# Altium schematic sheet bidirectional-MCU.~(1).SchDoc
size 431 x 279 mm; Date: Not shown in title block; ApprovedBy: Not shown in title block; CheckedBy: Not shown in title block; Author: Not shown in title block; CompanyName: Not shown in title block; Engineer: Not shown in title block; Organization: Not shown in title block; Address1: Not shown in title block; Address2: Not shown in title block; Address3: Not shown in title block; Address4: Not shown in title block; DocumentNumber: 1; Revision: Use project parameter SCH_Rev; SheetNumber: 1; SheetTotal: 6; PageSetup: Record=PageOptions¦CenterHorizontal=True¦CenterVertical=True¦PrintScale=0.96¦XCorrection=1.00¦YCorrection=1.00¦PrintKind=0¦BorderSize=5000000¦LeftOffset=0¦BottomOffset=0¦Orientation=2¦PaperLength=1000¦PaperWidth=1000¦Scale=100¦PaperSource=15¦PrintQuality=600¦MediaType=1¦DitherType=10¦PaperKind=11x17¦PrintScaleMode=1
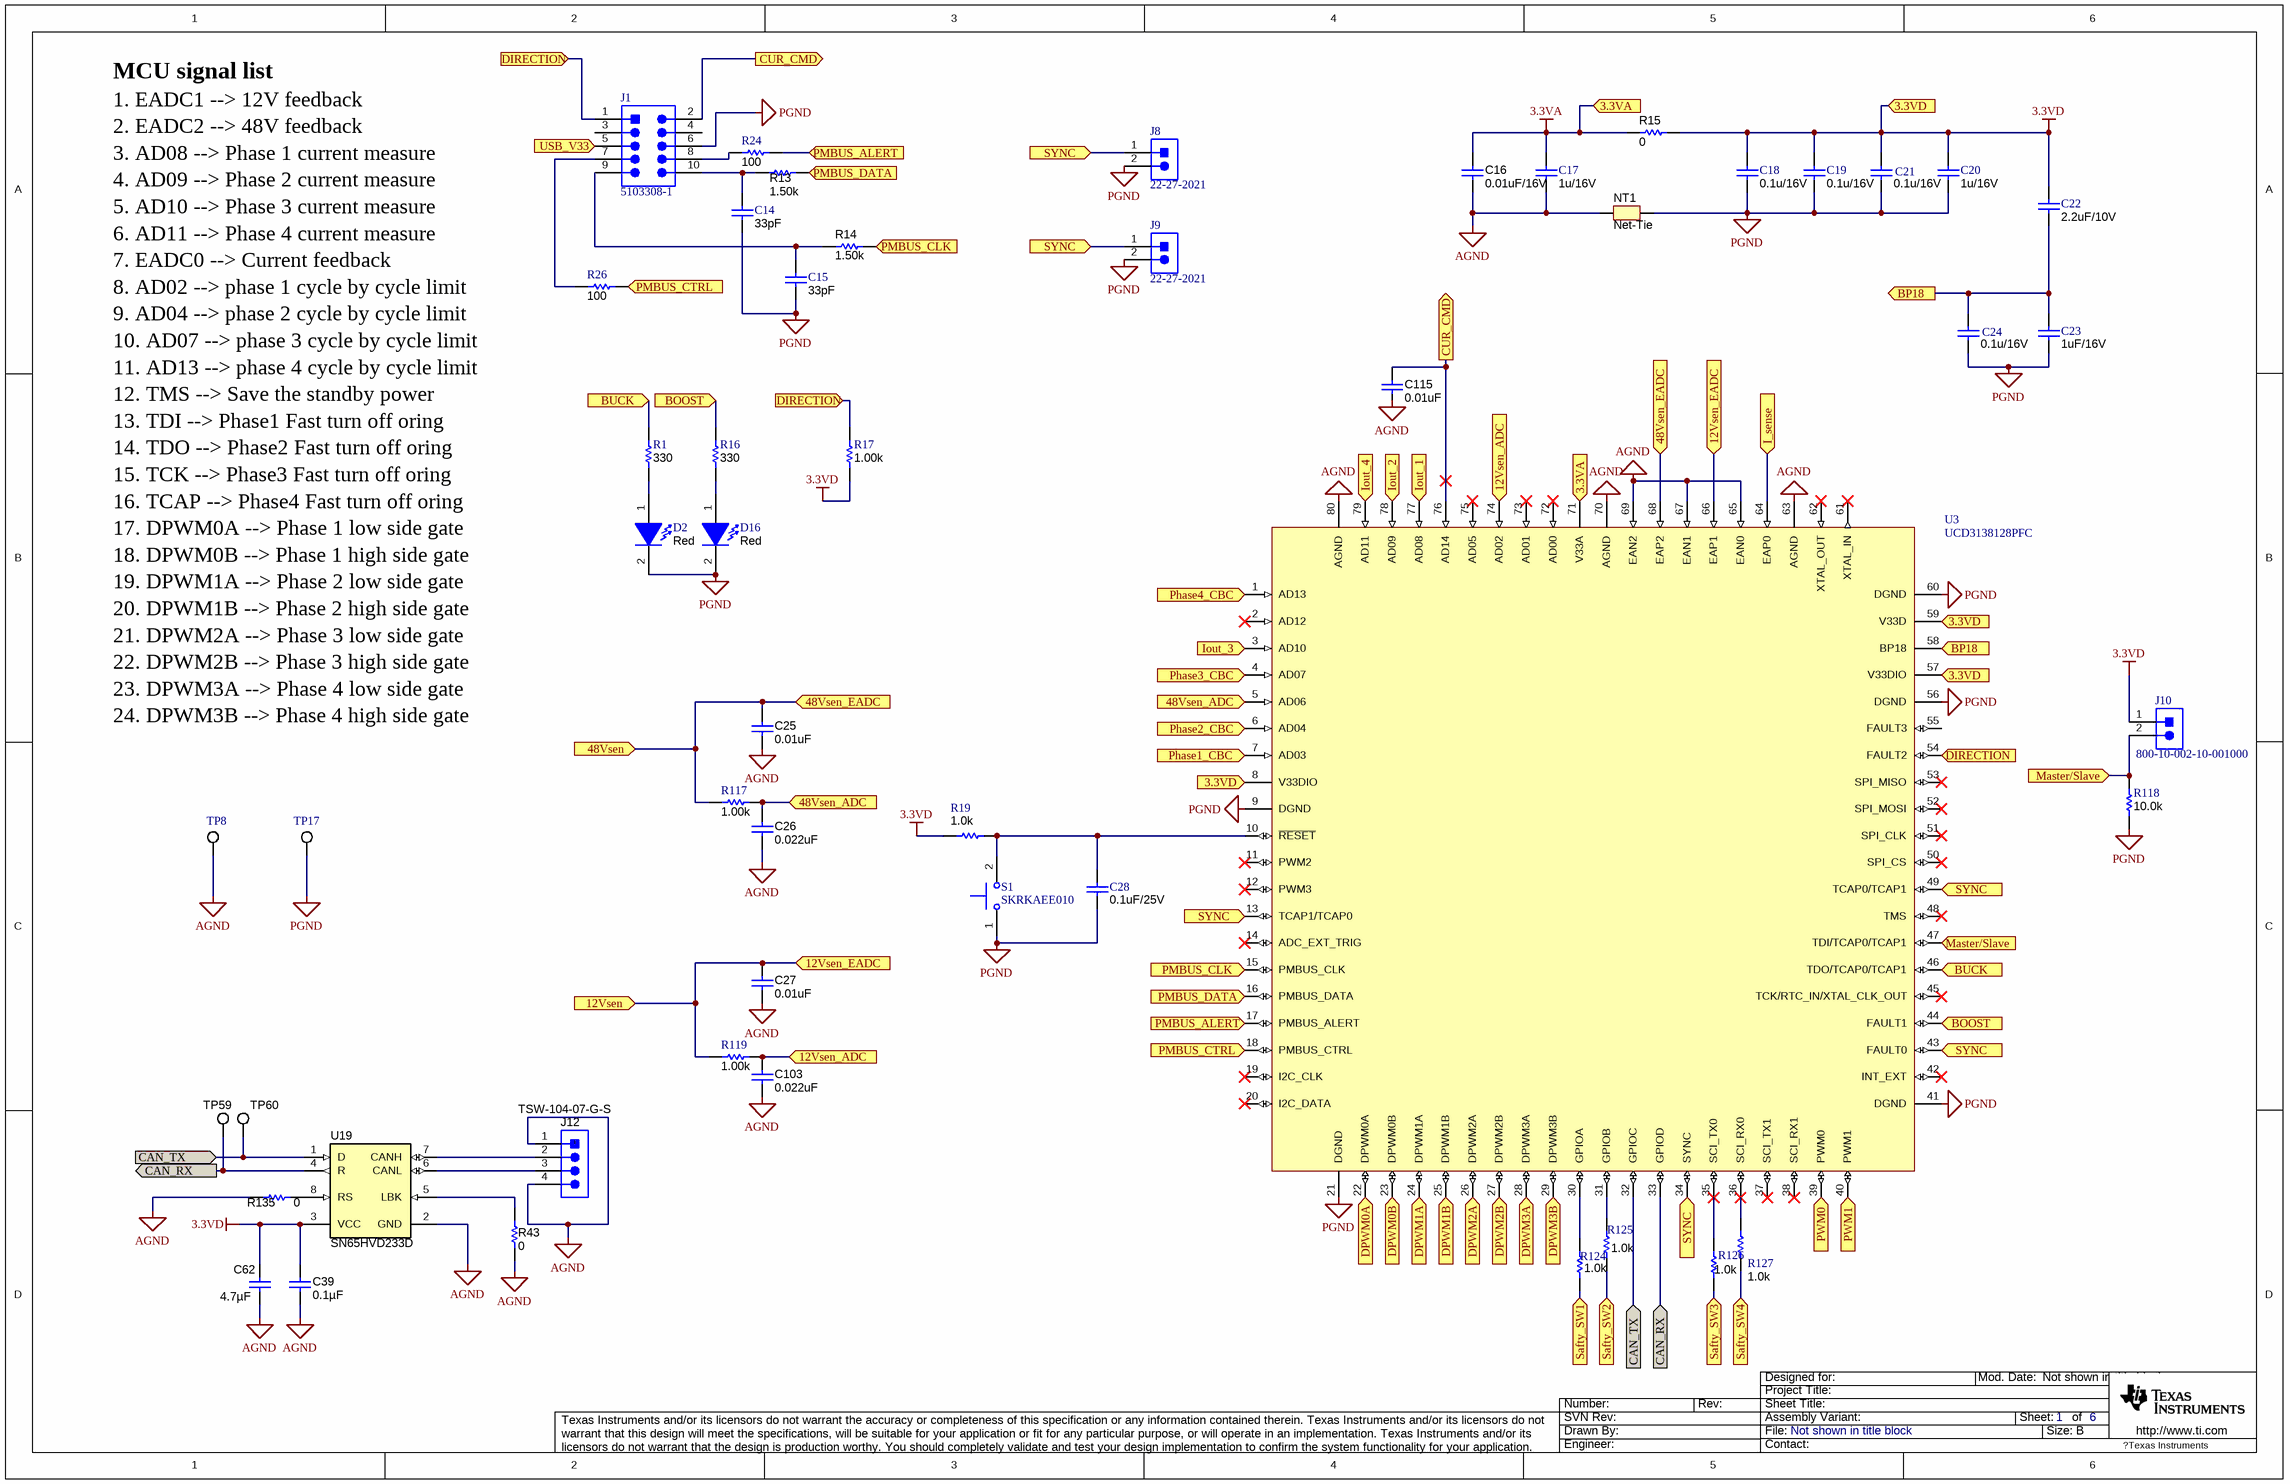
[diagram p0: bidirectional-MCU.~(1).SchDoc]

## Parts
C14  ValueDisplayed: 33pF  [0603]  (hidden comment: 06031A330JAT2A)
C15  ValueDisplayed: 33pF  [0603]  (hidden comment: 06031A330JAT2A)
C16  ValueDisplayed: 0.01uF/16V  [0603]  (hidden comment: 06031C103JAT2A)
C17  ValueDisplayed: 1u/16V  [0603]  (hidden comment: C0603C105K4PACTU)
C18  ValueDisplayed: 0.1u/16V  [0603]  (hidden comment: 0603YC104JAT2A)
C19  ValueDisplayed: 0.1u/16V  [0603]  (hidden comment: 0603YC104JAT2A)
C20  ValueDisplayed: 1u/16V  [0603]  (hidden comment: C0603C105K4PACTU)
C21  ValueDisplayed: 0.1u/16V  [0603]  (hidden comment: 0603YC104JAT2A)
C22  ValueDisplayed: 2.2uF/10V  [0603]  (hidden comment: C0603C225K8PACTU)
C23  ValueDisplayed: 1uF/16V  [0603]  (hidden comment: C0603C105K4PACTU)
C24  ValueDisplayed: 0.1u/16V  [0603]  (hidden comment: 0603YC104JAT2A)
C25  ValueDisplayed: 0.01uF  [0603]  (hidden comment: 06031C103JAT2A)
C26  ValueDisplayed: 0.022uF  [0603]  (hidden comment: C0603C223K3RACTU)
C27  ValueDisplayed: 0.01uF  [0603]  (hidden comment: 06031C103JAT2A)
C28  ValueDisplayed: 0.1uF/25V  [0603]  (hidden comment: 06033C104JAT2A)
C39  ValueDisplayed: 0.1µF  [0603]  (hidden comment: GRM188R71E104KA01D)
C62  ValueDisplayed: 4.7µF  [0805_HV]  (hidden comment: C2012X5R1E475K125AB)
C103  ValueDisplayed: 0.022uF  [0603]  (hidden comment: C0603C223K3RACTU)
C115  ValueDisplayed: 0.01uF  [0603]  (hidden comment: 06031C103JAT2A)
D2  value Red  [LED_LTST-C170]  (hidden comment: LTST-C170KRKT)
D16  value Red  [LED_LTST-C170]  (hidden comment: LTST-C170KRKT)
J1  5103308-1  [CONN_5103308-1]
J8  22-27-2021  [MOLEX_22-27-2021]
J9  22-27-2021  [MOLEX_22-27-2021]
J10  800-10-002-10-001000  [Mill-Max_800-10-002-10-001000]
J12  TSW-104-07-G-S  [TSW-104-07-G-S]
NT1  Net-Tie  [Net-Tie_10mil]  (net tie, no BOM)
R1  value 330  [0603]  (hidden comment: RC0603FR-07330RL)
R13  value 1.50k  [0603]  (hidden comment: RG1608P-152-B-T5)
R14  value 1.50k  [0603]  (hidden comment: RG1608P-152-B-T5)
R15  value 0  [0603]  (hidden comment: MCR03EZPJ000)
R16  value 330  [0603]  (hidden comment: RC0603FR-07330RL)
R17  value 1.00k  [0603]  (hidden comment: CRCW06031K00FKEA)
R19  value 1.0k  [0603]  (hidden comment: CRCW06031K00JNEA)
R24  value 100  [0603]  (hidden comment: CRCW0603100RFKEA)
R26  value 100  [0603]  (hidden comment: CRCW0603100RFKEA)
R43  value 0  [0805_HV]  (hidden comment: CRCW08050000Z0EA)
R117  value 1.00k  [0603]  (hidden comment: CRCW06031K00FKEA)
R118  value 10.0k  [0603]  (hidden comment: CRCW060310K0FKEA)
R119  value 1.00k  [0603]  (hidden comment: CRCW06031K00FKEA)
R124  value 1.0k  [0603L]  (hidden comment: CRCW06031K00JNEA)
R125  value 1.0k  [0603]  (hidden comment: CRCW06031K00JNEA)
R126  value 1.0k  [0603]  (hidden comment: CRCW06031K00JNEA)
R127  value 1.0k  [0603]  (hidden comment: CRCW06031K00JNEA)
R135  value 0  [0805_HV]  (hidden comment: CRCW08050000Z0EA)
S1  SKRKAEE010  [SW_SKRKAEE010]
TP8  5002  [Keystone5002]  (value not drawn)
TP17  5002  [Keystone5002]  (value not drawn)
TP59  5002  [Keystone5002]  (value not drawn)
TP60  5002  [Keystone5002]  (value not drawn)
U3  UCD3138128PFC  [PFC0080A_N]
U19  SN65HVD233D  [D0008A_L]

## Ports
3.3VA, 3.3VD, 12Vsen, 12Vsen_ADC, 12Vsen_EADC, 48Vsen, 48Vsen_ADC, 48Vsen_EADC, BOOST, BP18, BUCK, CAN_RX, CAN_TX, CAN_TX (in), CUR_CMD, DIRECTION, DPWM0A, DPWM0B, DPWM1A, DPWM1B, DPWM2A, DPWM2B, DPWM3A, DPWM3B, I_sense, Iout_1, Iout_2, Iout_3, Iout_4, Master/Slave, Phase1_CBC, Phase2_CBC, Phase3_CBC, Phase4_CBC, PMBUS_ALERT, PMBUS_CLK, PMBUS_CTRL, PMBUS_DATA, PWM0, PWM1, Safty_SW1, Safty_SW2, Safty_SW3, Safty_SW4, SYNC, USB_V33

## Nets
3.3VA: C16.1 C17.1 R15.1 U3.71(V33A) ; port 3.3VA
3.3VD: C18.1 C19.1 C20.1 C21.1 C22.2 C39.1 C62.1 J10.1 R15.2 R17.1 R19.1 U3.8(V33DIO) U3.57(V33DIO) U3.59(V33D) U19.3(VCC) ; port 3.3VD
AGND: C16.2 C17.2 C25.2 C26.2 C27.2 C39.2 C62.2 C103.2 J12.1 J12.4 NT1.1 R43.1 R135.2 TP8.1 U3.63(AGND) U3.65(EAN0) U3.67(EAN1) U3.69(EAN2) U3.70(AGND) U3.80(AGND) U19.2(GND)
PGND: C14.2 C15.2 C18.2 C19.2 C20.2 C21.2 C23.2 C24.2 C28.2 D2.2(K) D16.2(K) J1.6 J8.2 J9.2 NT1.2 R118.1 S1.1 TP17.1 U3.9(DGND) U3.21(DGND) U3.41(DGND) U3.56(DGND) U3.60(DGND)
12Vsen: C27.1 R119.1 U3.66(EAP1) ; port 12Vsen_EADC, port 12Vsen
12Vsen_ADC: C103.1 R119.2 U3.74(AD02) ; port 12Vsen_ADC
48Vsen: C25.1 R117.1 U3.68(EAP2) ; port 48Vsen_EADC, port 48Vsen
48Vsen_ADC: C26.1 R117.2 U3.5(AD06) ; port 48Vsen_ADC
BOOST: R16.2 U3.44(FAULT1) ; port BOOST
BP18: C22.1 C23.1 C24.1 U3.58(BP18) ; port BP18
BUCK: R1.2 U3.46(TDO/TCAP0/TCAP1) ; port BUCK
CAN_RX: TP59.1 U3.33(GPIOD) U19.4(R) ; port CAN_RX
CAN_TX: TP60.1 U3.32(GPIOC) U19.1(D) ; port CAN_TX
CUR_CMD: C115.1 J1.2 U3.76(AD14) ; port CUR_CMD
DIRECTION: J1.1 R17.2 U3.54(FAULT2) ; port DIRECTION
DPWM0A: U3.22(DPWM0A) ; port DPWM0A
DPWM0B: U3.23(DPWM0B) ; port DPWM0B
DPWM1A: U3.24(DPWM1A) ; port DPWM1A
DPWM1B: U3.25(DPWM1B) ; port DPWM1B
DPWM2A: U3.26(DPWM2A) ; port DPWM2A
DPWM2B: U3.27(DPWM2B) ; port DPWM2B
DPWM3A: U3.28(DPWM3A) ; port DPWM3A
DPWM3B: U3.29(DPWM3B) ; port DPWM3B
I_sense: U3.64(EAP0) ; port I_sense
Iout_1: U3.77(AD08) ; port Iout_1
Iout_2: U3.78(AD09) ; port Iout_2
Iout_3: U3.3(AD10) ; port Iout_3
Iout_4: U3.79(AD11) ; port Iout_4
Master/Slave: J10.2 R118.2 U3.47(TDI/TCAP0/TCAP1) ; port Master/Slave
Phase1_CBC: U3.7(AD03) ; port Phase1_CBC
Phase2_CBC: U3.6(AD04) ; port Phase2_CBC
Phase3_CBC: U3.4(AD07) ; port Phase3_CBC
Phase4_CBC: U3.1(AD13) ; port Phase4_CBC
PMBUS_ALERT: R24.2 U3.17(PMBUS_ALERT) ; port PMBUS_ALERT
PMBUS_CLK: R14.2 U3.15(PMBUS_CLK) ; port PMBUS_CLK
PMBUS_CTRL: R26.2 U3.18(PMBUS_CTRL) ; port PMBUS_CTRL
PMBUS_DATA: R13.2 U3.16(PMBUS_DATA) ; port PMBUS_DATA
PWM0: U3.39(PWM0) ; port PWM0
PWM1: U3.40(PWM1) ; port PWM1
Safty_SW1: R124.1 ; port Safty_SW1
Safty_SW2: R125.1 ; port Safty_SW2
Safty_SW3: R126.1 ; port Safty_SW3
Safty_SW4: R127.1 ; port Safty_SW4
SYNC: J8.1 J9.1 U3.13(TCAP1/TCAP0) U3.34(SYNC) U3.43(FAULT0) U3.49(TCAP0/TCAP1) ; port SYNC
USB_V33: J1.5 ; port USB_V33
NetC14_1: C14.1 J1.10 R13.1
NetC15_1: C15.1 J1.9 R14.1
NetC28_1: C28.1 R19.2 S1.2 U3.10(~{RESET})
NetD2_1: D2.1(A) R1.1
NetD16_1: D16.1(A) R16.1
NetJ1_7: J1.7 R26.1
NetJ1_8: J1.8 R24.1
NetJ12_2: J12.2 U19.7(CANH)
NetJ12_3: J12.3 U19.6(CANL)
NetR43_2: R43.2 U19.5(LBK)
NetR124_2: R124.2 U3.30(GPIOA)
NetR125_2: R125.2 U3.31(GPIOB)
NetR126_2: R126.2 U3.35(SCI_TX0)
NetR127_2: R127.2 U3.36(SCI_RX0)
NetR135_1: R135.1 U19.8(RS)

Not connected (* = marked no-connect by the designer): C115 2; J1 3 4; U3 2(AD12)* 11(PWM2)* 12(PWM3)* 14(ADC_EXT_TRIG)* 19(I2C_CLK)* 20(I2C_DATA)* 37(SCI_TX1)* 38(SCI_RX1)* 42(INT_EXT)* 45(TCK/RTC_IN/XTAL_CLK_OUT)* 48(TMS)* 50(SPI_CS)* 51(SPI_CLK)* 52(SPI_MOSI)* 53(SPI_MISO)* 55(FAULT3) 61(XTAL_IN)* 62(XTAL_OUT)* 72(AD00)* 73(AD01)* 75(AD05)*

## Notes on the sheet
- MCU signal list
- 1. EADC1 --> 12V feedback
- 2. EADC2 --> 48V feedback
- 3. AD08 --> Phase 1 current measure
- 4. AD09 --> Phase 2 current measure
- 5. AD10 --> Phase 3 current measure
- 7. EADC0 --> Current feedback
- (near R26) 8. AD02 --> phase 1 cycle by cycle limit
- 6. AD11 --> Phase 4 current measure
- (near R26) 9. AD04 --> phase 2 cycle by cycle limit
- (near R26) 10. AD07 --> phase 3 cycle by cycle limit
- 12. TMS --> Save the standby power
- 13. TDI --> Phase1 Fast turn off oring
- 11. AD13 --> phase 4 cycle by cycle limit
- 14. TDO --> Phase2 Fast turn off oring
- 15. TCK --> Phase3 Fast turn off oring
- 17. DPWM0A --> Phase 1 low side gate
- 18. DPWM0B --> Phase 1 high side gate
- 16. TCAP --> Phase4 Fast turn off oring
- 19. DPWM1A --> Phase 2 low side gate
- 20. DPWM1B --> Phase 2 high side gate
- 21. DPWM2A --> Phase 3 low side gate
- 22. DPWM2B --> Phase 3 high side gate
- 23. DPWM3A --> Phase 4 low side gate
- 24. DPWM3B --> Phase 4 high side gate
- Labels drawn without touching a wire or pin: AGND

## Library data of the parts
C14 C15 = 06031A330JAT2A: CAP, CERM, 33pF, 100V, +/-5%, C0G/NP0, 0603; Manufacturer: AVX; Polarized: N; CompType: Capacitor; U/M: EA; Cap_F: 0.000000000033; Tolerance_%: 5; ESR_Ohm: 0.209; Value1: 0.209 ohm; VDC_V: 100; TaMin_C: -55; TaMax_C: 125
C16 C25 C27 C115 = 06031C103JAT2A: CAP, CERM, 0.01uF, 100V, +/-5%, X7R, 0603; Manufacturer: AVX; Polarized: N; CompType: Capacitor; U/M: EA; Cap_F: 0.00000001; Tolerance_%: 5; ESR_Ohm: 0.098; Value1: 0.098 ohm; VDC_V: 100; TaMin_C: -55; TaMax_C: 125
C17 C20 C23 = C0603C105K4PACTU: CAP, CERM, 1uF, 16V, +/-10%, X5R, 0603; Manufacturer: Kemet; Polarized: N; CompType: Capacitor; U/M: EA; Cap_F: 0.000001; Tolerance_%: 10; Value1: Unknown; VDC_V: 16; TaMin_C: -55; TaMax_C: 85
C18 C19 C21 C24 = 0603YC104JAT2A: CAP, CERM, 0.1uF, 16V, +/-5%, X7R, 0603; Manufacturer: AVX; Polarized: N; CompType: Capacitor; U/M: EA; Cap_F: 0.0000001; Tolerance_%: 5; ESR_Ohm: 0.039; Value1: 0.039 ohm; VDC_V: 16; TaMin_C: -55; TaMax_C: 125
C22 = C0603C225K8PACTU: CAP, CERM, 2.2uF, 10V, +/-10%, X5R, 0603; Manufacturer: Kemet; Polarized: N; CompType: Capacitor; U/M: EA; Cap_F: 0.0000022; Tolerance_%: 10; Value1: Unknown; TaMin_C: -55; TaMax_C: 85
C26 C103 = C0603C223K3RACTU: CAP, CERM, 0.022uF, 25V, +/-10%, X7R, 0603; Manufacturer: Kemet; Polarized: N; CompType: Capacitor; U/M: EA; Cap_F: 0.000000022; Tolerance_%: 10; Value1: Unknown; VDC_V: 25; TaMin_C: -55; TaMax_C: 125
C28 = 06033C104JAT2A: CAP, CERM, 0.1uF, 25V, +/-5%, X7R, 0603; Manufacturer: AVX; Polarized: N; CompType: Capacitor; U/M: EA; Cap_F: 0.0000001; Tolerance_%: 5; ESR_Ohm: 0.05; Value1: 0.05 ohm; VDC_V: 25; TaMin_C: -55; TaMax_C: 125
C39 = GRM188R71E104KA01D: CAP, CERM, 0.1uF, 25V, +/-10%, X7R, 0603; Manufacturer: MuRata; Polarized: N; CompType: Capacitor; U/M: EA; Cap_F: 0.0000001; Tolerance_%: 10; Value1: Unknown; VDC_V: 25; TaMin_C: -55; TaMax_C: 125
C62 = C2012X5R1E475K125AB: CAP, CERM, 4.7uF, 25V, +/-10%, X5R, 0805; Manufacturer: TDK; Polarized: N; CompType: Capacitor; U/M: EA; Cap_F: 0.0000047; Tolerance_%: 10; Value1: Unknown; VDC_V: 25; TaMin_C: -55; TaMax_C: 85; Cap_Case: 0805
D2 D16 = LTST-C170KRKT: LED, Red, SMD; Manufacturer: Lite-On; Type: AlInGaP; Vf_V: 2; Value2: 2V; Io_A: 0.02; Value1: W; U/M: EA
J1 = 5103308-1: Header (shrouded), 100mil, 5x2, Gold, TH; Manufacturer: TE Connectivity; SymbolCreator: a0412235; CompType: Connector; U/M: EA
J8 J9 = 22-27-2021: Header,2x1, 100mil, TH; Manufacturer: Molex; SymbolCreator: a0412235; U/M: EA
J10 = 800-10-002-10-001000: Header, 2x1, 100mil, SMT; Manufacturer: Mill-Max; SymbolCreator: a0412235; U/M: EA
J12 = TSW-104-07-G-S: Header, TH, 100mil, 4x1, Gold plated, 230 mil above insulator; Manufacturer: Samtec; SymbolCreator: a0412235; U/M: EA
NT1 = Net-Tie: Single point connection between nets.; SymbolCreator: codlsc
R1 R16 = RC0603FR-07330RL: RES, 330 ohm, 1%, 0.1W, 0603; Manufacturer: Yageo America; CompType: Resistor; Value_Code: 330R; Tolerance_%: 1; Power_W: 0.1; VDC_V: 150; TempCo: 200 ppm/C; U/M: EA
R13 R14 = RG1608P-152-B-T5: RES, 1.50k ohm, 0.1%, 0.1W, 0603; Manufacturer: Susumu Co Ltd; CompType: Resistor; Res_ohm: 1500; Value_Code: 1k50; Tolerance_%: 0.1; VDC_V: 75; TempCo: 25 ppm/C; EIA_Code: E192; U/M: EA
R15 = MCR03EZPJ000: RES, 0 ohm, 5%, 0.1W, 0603; Manufacturer: Rohm; CompType: Resistor; Value_Code: 0000; Tolerance_%: 5; Power_W: 0.1; VDC_V: 50; TempCo: 400 ppm/C; EIA_Code: E24; U/M: EA
R17 R117 R119 = CRCW06031K00FKEA: RES, 1.00k ohm, 1%, 0.1W, 0603; Manufacturer: Vishay-Dale; CompType: Resistor; Res_ohm: 1000; Value_Code: 1k00; Tolerance_%: 1; Power_W: 0.1; VDC_V: 75; TempCo: 100 ppm/C; EIA_Code: E96; U/M: EA
R19 R124-R127 = CRCW06031K00JNEA: RES, 1.0k ohm, 5%, 0.1W, 0603; Manufacturer: Vishay-Dale; CompType: Resistor; Res_ohm: 1000; Value_Code: 1k00; Tolerance_%: 5; Power_W: 0.1; VDC_V: 75; TempCo: 200 ppm/C; EIA_Code: E24; U/M: EA
R24 R26 = CRCW0603100RFKEA: RES, 100 ohm, 1%, 0.1W, 0603; Manufacturer: Vishay-Dale; CompType: Resistor; Value_Code: 100R; Tolerance_%: 1; Power_W: 0.1; VDC_V: 75; TempCo: 100 ppm/C; EIA_Code: E96; U/M: EA
R43 R135 = CRCW08050000Z0EA: RES, 0 ohm, 5%, 0.125W, 0805; Manufacturer: Vishay-Dale; CompType: Resistor; Value_Code: 0000; Tolerance_%: 5; Power_W: 0.125; VDC_V: 150; TempCo: 200 ppm/C; EIA_Code: E24; U/M: EA
R118 = CRCW060310K0FKEA: RES, 10.0k ohm, 1%, 0.1W, 0603; Manufacturer: Vishay-Dale; CompType: Resistor; Res_ohm: 10000; Value_Code: 10k0; Tolerance_%: 1; Power_W: 0.1; VDC_V: 75; TempCo: 100 ppm/C; EIA_Code: E96; U/M: EA
S1 = SKRKAEE010: Switch, Push Button, SMD; Manufacturer: Alps; SymbolCreator: a0412235; Circuit: SPST-NO; VDC_V: 12; SwitchFunction: Off-Mom; PositionCount: 1; CurrentRating_mA: 50
TP8 TP17 TP59 TP60 = 5002: Test Point, Miniature, White, TH; Manufacturer: Keystone; CompType: Test Point Loop; U/M: EA
U3 = UCD3138128PFC: UCD3138128PFC, PFC0080; Alternate Manufacturer: None; Manufacturer: Texas Instruments; SymbolCreator: a0411947; CompType: IC; U/M: EA
U19 = SN65HVD233D: 3.3V CAN Transceiver with Standby Mode, Loop-back, 6 mA, -40 to 125 degC, 8-pin SOIC (D), Green (RoHS & no Sb/Br); Manufacturer: Texas Instruments; Alternate PartNumber: Equivalent; Drivers Per Package: 1; Bus Fault Voltage(V): +/-30; Transient Pulse Protection(V): -100 to 100; ICC(Max)(mA): 6; Supply Voltage(s)(V): 3.3; Rating: Catalog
